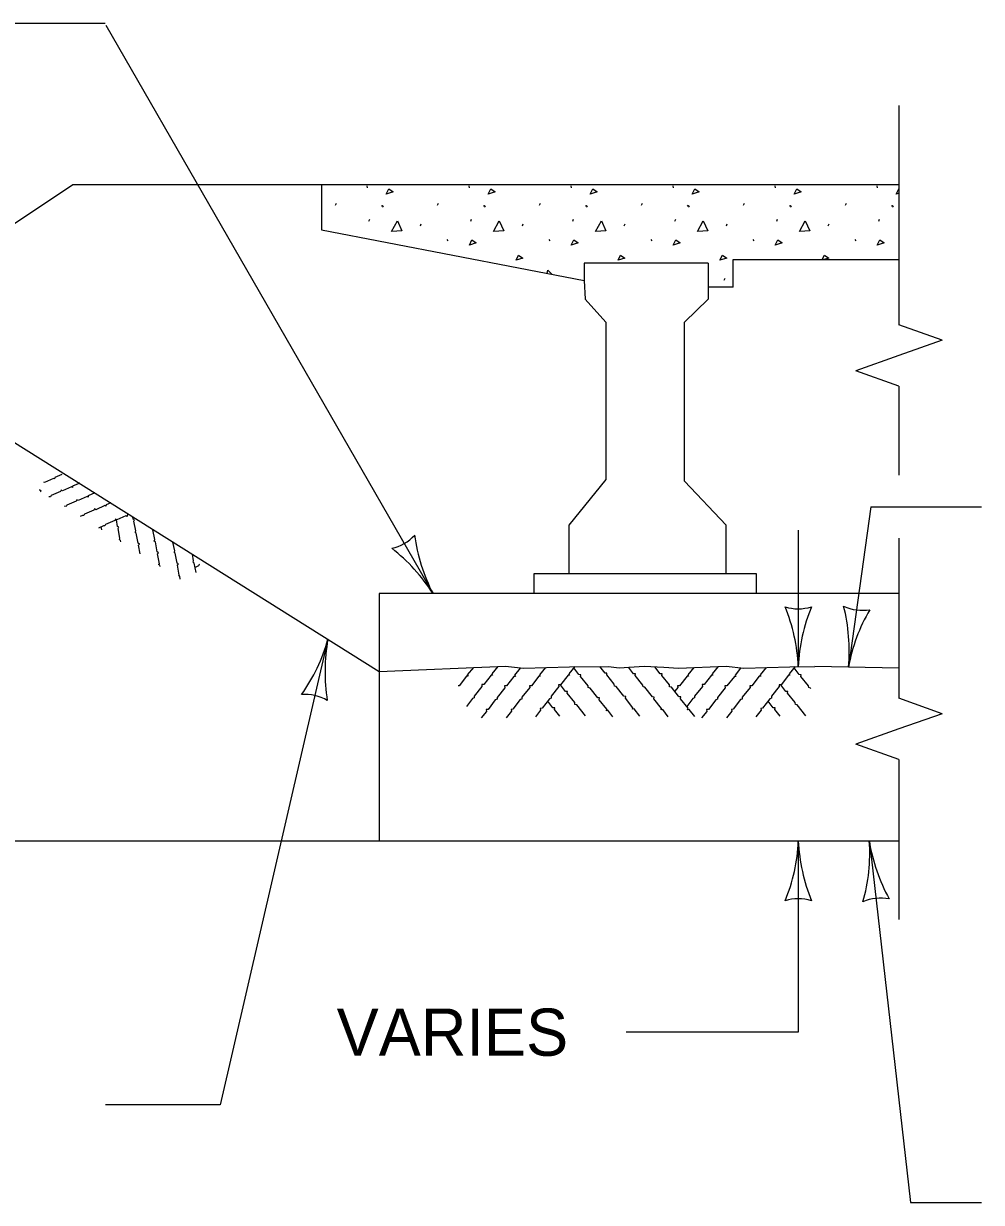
# Model space of a CAD drawing. Extents: x 49991.4 to 50021, y 49987.6 to 50011.4.
# Drawn here: x 50005.968 to 50007.186, y 50005.606 to 50007.104 of the extents above; entities that cross this region are included whole.
import ezdxf

# ---------------------------------------------------------------- set-up
doc = ezdxf.new("R2010")
doc.units = 0
for name, color, linetype in [('Level 1', 7, 'Continuous'), ('Level 2', 7, 'Continuous'), ('Level 3', 7, 'Continuous'), ('Level 4', 7, 'Continuous'), ('Level 6', 7, 'Continuous')]:
    doc.layers.add(name, color=color, linetype=linetype)

msp = doc.modelspace()

# ---------------------------------------------------------------- linework, layer by layer
at = {"layer": 'Level 1'}
for p, q in [((50005.6313, 50006.6335), (50006.0307, 50006.8995)), ((50006.0307, 50006.8995), (50006.3466, 50006.8995)), ((50006.3466, 50006.8995), (50007.0807, 50006.8995)), ((50006.3466, 50006.8995), (50006.3466, 50006.8416)), ((50006.4043, 50006.8976), (50006.4046, 50006.8951)), ((50006.534, 50006.8976), (50006.5342, 50006.8951)), ((50006.6636, 50006.8976), (50006.6639, 50006.8951)), ((50006.7933, 50006.8976), (50006.7935, 50006.8951)), ((50006.9229, 50006.8976), (50006.9232, 50006.8951)), ((50007.0526, 50006.8976), (50007.0529, 50006.8951)), ((50006.3646, 50006.873), (50006.3657, 50006.8754)), ((50006.4228, 50006.873), (50006.4239, 50006.8714)), ((50006.4239, 50006.8724), (50006.4249, 50006.8707)), ((50006.4942, 50006.873), (50006.4953, 50006.8754)), ((50006.5524, 50006.873), (50006.5535, 50006.8714)), ((50006.5535, 50006.8724), (50006.5546, 50006.8707)), ((50006.6239, 50006.873), (50006.625, 50006.8754)), ((50006.6821, 50006.873), (50006.6832, 50006.8714)), ((50006.6832, 50006.8724), (50006.6843, 50006.8707)), ((50006.7535, 50006.873), (50006.7546, 50006.8754)), ((50006.8117, 50006.873), (50006.8128, 50006.8714)), ((50006.8128, 50006.8724), (50006.8139, 50006.8707)), ((50006.8832, 50006.873), (50006.8843, 50006.8754)), ((50006.9414, 50006.873), (50006.9425, 50006.8714)), ((50006.9425, 50006.8724), (50006.9436, 50006.8707)), ((50007.0129, 50006.873), (50007.0139, 50006.8754)), ((50007.0711, 50006.873), (50007.0721, 50006.8714)), ((50007.0721, 50006.8724), (50007.0732, 50006.8707)), ((50006.4068, 50006.8529), (50006.4079, 50006.8554)), ((50006.4723, 50006.8467), (50006.4734, 50006.8491)), ((50006.5365, 50006.8529), (50006.5375, 50006.8554)), ((50006.602, 50006.8467), (50006.6031, 50006.8491)), ((50006.6661, 50006.8529), (50006.6672, 50006.8554)), ((50006.7316, 50006.8467), (50006.7327, 50006.8491)), ((50006.7958, 50006.8529), (50006.7969, 50006.8554)), ((50006.8613, 50006.8467), (50006.8624, 50006.8491)), ((50006.9254, 50006.8529), (50006.9265, 50006.8554)), ((50006.9909, 50006.8467), (50006.992, 50006.8491)), ((50007.0551, 50006.8529), (50007.0562, 50006.8554)), ((50006.3466, 50006.8416), (50006.6807, 50006.7771)), ((50006.5061, 50006.8294), (50006.5072, 50006.8277)), ((50006.6358, 50006.8294), (50006.6369, 50006.8277)), ((50006.7655, 50006.8294), (50006.7665, 50006.8277)), ((50006.8951, 50006.8294), (50006.8962, 50006.8277)), ((50007.0248, 50006.8294), (50007.0259, 50006.8277)), ((50006.8699, 50006.7689), (50006.8699, 50006.8038)), ((50006.8699, 50006.8038), (50007.0807, 50006.8038)), ((50006.6807, 50006.7995), (50006.6807, 50006.7771)), ((50006.8383, 50006.7995), (50006.6807, 50006.7995)), ((50006.8383, 50006.7995), (50006.8383, 50006.7537)), ((50006.6807, 50006.7771), (50006.6818, 50006.7537)), ((50006.8586, 50006.7779), (50006.8597, 50006.7804)), ((50006.8699, 50006.7689), (50006.8383, 50006.7689)), ((50006.6818, 50006.7537), (50006.7083, 50006.7244)), ((50006.8383, 50006.7537), (50006.8083, 50006.7244)), ((50006.7083, 50006.7244), (50006.7083, 50006.5244)), ((50006.8083, 50006.5222), (50006.8083, 50006.7244)), ((50005.8202, 50006.6567), (50006.4201, 50006.2806)), ((50006.7083, 50006.5244), (50006.6612, 50006.4665)), ((50006.8083, 50006.5222), (50006.8612, 50006.4665)), ((50006.6612, 50006.4665), (50006.6612, 50006.405)), ((50006.8612, 50006.405), (50006.8612, 50006.4665)), ((50006.6171, 50006.3795), (50006.6171, 50006.405)), ((50006.6171, 50006.405), (50006.8994, 50006.405)), ((50006.6612, 50006.405), (50006.8612, 50006.405)), ((50006.8994, 50006.405), (50006.8994, 50006.3795)), ((50007.0807, 50006.3795), (50006.4201, 50006.3795)), ((50006.4201, 50006.3795), (50006.4201, 50006.2806)), ((50007.0807, 50006.2848), (50006.9738, 50006.2869))]:
    msp.add_line(p, q, dxfattribs=at)
for points in [[(50006.429, 50006.8871), (50006.4323, 50006.8938), (50006.4377, 50006.8898), (50006.429, 50006.8871)], [(50006.5587, 50006.8871), (50006.5619, 50006.8938), (50006.5673, 50006.8898), (50006.5587, 50006.8871)], [(50006.6883, 50006.8871), (50006.6916, 50006.8938), (50006.697, 50006.8898), (50006.6883, 50006.8871)], [(50006.818, 50006.8871), (50006.8212, 50006.8938), (50006.8266, 50006.8898), (50006.818, 50006.8871)], [(50006.9476, 50006.8871), (50006.9509, 50006.8938), (50006.9563, 50006.8898), (50006.9476, 50006.8871)], [(50007.0773, 50006.8871), (50007.0805, 50006.8938), (50007.0807, 50006.8937)], [(50007.0807, 50006.8881), (50007.0773, 50006.8871)], [(50006.4358, 50006.8394), (50006.4431, 50006.8532), (50006.4488, 50006.8405), (50006.436, 50006.8394)], [(50006.5654, 50006.8394), (50006.5727, 50006.8532), (50006.5784, 50006.8405), (50006.5657, 50006.8394)], [(50006.6951, 50006.8394), (50006.7024, 50006.8532), (50006.7081, 50006.8405), (50006.6954, 50006.8394)], [(50006.8247, 50006.8394), (50006.832, 50006.8532), (50006.8377, 50006.8405), (50006.825, 50006.8394)], [(50006.9544, 50006.8394), (50006.9617, 50006.8532), (50006.9674, 50006.8405), (50006.9547, 50006.8394)], [(50006.5346, 50006.8223), (50006.5378, 50006.8291), (50006.5432, 50006.825), (50006.5346, 50006.8223)], [(50006.6642, 50006.8223), (50006.6675, 50006.8291), (50006.6729, 50006.825), (50006.6642, 50006.8223)], [(50006.7939, 50006.8223), (50006.7971, 50006.8291), (50006.8025, 50006.825), (50006.7939, 50006.8223)], [(50006.9235, 50006.8223), (50006.9268, 50006.8291), (50006.9322, 50006.825), (50006.9235, 50006.8223)], [(50007.0532, 50006.8223), (50007.0564, 50006.8291), (50007.0618, 50006.825), (50007.0532, 50006.8223)], [(50006.5939, 50006.803), (50006.5972, 50006.8097), (50006.6026, 50006.8057), (50006.5939, 50006.803)], [(50006.7236, 50006.803), (50006.7268, 50006.8097), (50006.7322, 50006.8057), (50006.7236, 50006.803)], [(50006.8532, 50006.803), (50006.8565, 50006.8097), (50006.8619, 50006.8057), (50006.8532, 50006.803)], [(50006.9832, 50006.8038), (50006.9861, 50006.8097), (50006.9915, 50006.8057), (50006.9854, 50006.8038)], [(50006.6337, 50006.7861), (50006.6343, 50006.7906), (50006.6398, 50006.785)], [(50006.0166, 50006.5306), (50006.0075, 50006.5269), (50006.0074, 50006.5252), (50006.0061, 50006.5259), (50005.9945, 50006.5208), (50005.9936, 50006.5212)], [(50006.0393, 50006.5198), (50006.0302, 50006.5161), (50006.0302, 50006.5144), (50006.0288, 50006.5151), (50006.0173, 50006.51), (50006.0155, 50006.5109), (50006.0148, 50006.5091), (50006.003, 50006.504), (50006.0021, 50006.5023), (50006.0003, 50006.5026), (50006.0001, 50006.5025)], [(50005.9896, 50006.509), (50005.9903, 50006.5098), (50005.9887, 50006.5109), (50005.9885, 50006.5117)], [(50006.0586, 50006.5074), (50006.0502, 50006.5039), (50006.0501, 50006.5022), (50006.0488, 50006.5029), (50006.0372, 50006.4978), (50006.0355, 50006.4987), (50006.0348, 50006.4969), (50006.023, 50006.4918), (50006.0221, 50006.4902), (50006.0202, 50006.4904), (50006.0198, 50006.4901)], [(50006.0787, 50006.4946), (50006.0727, 50006.4922), (50006.0726, 50006.4906), (50006.0713, 50006.4913), (50006.0597, 50006.4861), (50006.0579, 50006.4871), (50006.0573, 50006.4853), (50006.0454, 50006.4802), (50006.0446, 50006.4785), (50006.0427, 50006.4788), (50006.0399, 50006.4775)], [(50006.1018, 50006.4801), (50006.0994, 50006.4792), (50006.0994, 50006.4775), (50006.098, 50006.4782), (50006.0865, 50006.4731), (50006.0847, 50006.474), (50006.084, 50006.4722), (50006.0722, 50006.4671), (50006.0713, 50006.4654), (50006.0695, 50006.4657), (50006.0633, 50006.4628)], [(50006.0916, 50006.4451), (50006.0912, 50006.4469), (50006.0898, 50006.4482), (50006.0904, 50006.4499), (50006.088, 50006.4622), (50006.0891, 50006.4637), (50006.0874, 50006.4647), (50006.086, 50006.4732)], [(50006.1159, 50006.4299), (50006.1138, 50006.4409), (50006.1151, 50006.4424), (50006.1135, 50006.4435), (50006.1112, 50006.4561), (50006.1098, 50006.4574), (50006.1104, 50006.4591), (50006.108, 50006.4714), (50006.1091, 50006.473), (50006.1074, 50006.4739), (50006.1069, 50006.4769)], [(50006.0674, 50006.4603), (50006.0667, 50006.4644)], [(50006.1415, 50006.4139), (50006.1411, 50006.4158), (50006.1395, 50006.4163), (50006.1405, 50006.4174), (50006.1381, 50006.4298), (50006.1394, 50006.4313), (50006.1378, 50006.4324), (50006.1355, 50006.4451), (50006.1341, 50006.4463), (50006.1348, 50006.448), (50006.1323, 50006.4604), (50006.1327, 50006.4608)], [(50006.167, 50006.3978), (50006.1664, 50006.4016), (50006.1647, 50006.402), (50006.1657, 50006.4031), (50006.1634, 50006.4155), (50006.1647, 50006.4171), (50006.1631, 50006.4181), (50006.1608, 50006.4308), (50006.1594, 50006.432), (50006.16, 50006.4338), (50006.1578, 50006.445)], [(50006.1871, 50006.4063), (50006.1849, 50006.4181), (50006.1835, 50006.4194), (50006.1841, 50006.4211), (50006.1825, 50006.4296)], [(50006.1919, 50006.4159), (50006.191, 50006.4164), (50006.1904, 50006.4146), (50006.1859, 50006.4127)], [(50006.4201, 50006.2806), (50006.5807, 50006.2873), (50006.6035, 50006.2848), (50006.662, 50006.2866), (50006.7114, 50006.287), (50006.725, 50006.2852), (50006.757, 50006.2874), (50006.7817, 50006.2859), (50006.8005, 50006.2848)], [(50006.5397, 50006.2856), (50006.532, 50006.2763), (50006.5329, 50006.2745), (50006.5311, 50006.2745), (50006.5216, 50006.2624), (50006.5203, 50006.2624)], [(50006.5708, 50006.2869), (50006.5632, 50006.2777), (50006.5641, 50006.2759), (50006.5623, 50006.2759), (50006.5528, 50006.2638), (50006.5503, 50006.2638), (50006.5506, 50006.2614), (50006.5408, 50006.2492), (50006.5408, 50006.2469), (50006.5386, 50006.2461), (50006.5309, 50006.2361)], [(50006.5993, 50006.2846), (50006.5922, 50006.276), (50006.5931, 50006.2742), (50006.5913, 50006.2742), (50006.5818, 50006.2621), (50006.5793, 50006.2621), (50006.5796, 50006.2598), (50006.5698, 50006.2475), (50006.5698, 50006.2452), (50006.5676, 50006.2444), (50006.5583, 50006.2323), (50006.556, 50006.2321), (50006.5564, 50006.2298), (50006.5497, 50006.2215)], [(50006.6316, 50006.2857), (50006.6239, 50006.2763), (50006.6248, 50006.2745), (50006.6229, 50006.2745), (50006.6134, 50006.2624), (50006.611, 50006.2624), (50006.6113, 50006.2601), (50006.6014, 50006.2478), (50006.6014, 50006.2455), (50006.5993, 50006.2447), (50006.5899, 50006.2326), (50006.5876, 50006.2324), (50006.5881, 50006.2301), (50006.5813, 50006.2218)], [(50006.6686, 50006.2867), (50006.661, 50006.2776), (50006.6619, 50006.2757), (50006.6601, 50006.2757), (50006.6506, 50006.2636), (50006.6481, 50006.2636), (50006.6484, 50006.2613), (50006.6386, 50006.249), (50006.6386, 50006.2467), (50006.6365, 50006.2459), (50006.6271, 50006.2338), (50006.6248, 50006.2336), (50006.6252, 50006.2313), (50006.6185, 50006.223)], [(50006.717, 50006.223), (50006.7108, 50006.2312), (50006.7088, 50006.2307), (50006.7092, 50006.2325), (50006.6995, 50006.2445), (50006.7001, 50006.2469), (50006.6978, 50006.2472), (50006.688, 50006.2595), (50006.6858, 50006.26), (50006.6855, 50006.2623), (50006.6758, 50006.2741), (50006.6762, 50006.2764), (50006.6738, 50006.2765), (50006.6673, 50006.285)], [(50006.7513, 50006.2238), (50006.7441, 50006.2332), (50006.7421, 50006.2327), (50006.7425, 50006.2345), (50006.7329, 50006.2465), (50006.7334, 50006.2489), (50006.7311, 50006.2491), (50006.7214, 50006.2615), (50006.7191, 50006.262), (50006.7189, 50006.2643), (50006.7092, 50006.2761), (50006.7095, 50006.2784), (50006.7072, 50006.2785), (50006.7006, 50006.2869)], [(50006.7875, 50006.2229), (50006.7804, 50006.2323), (50006.7784, 50006.2318), (50006.7788, 50006.2336), (50006.7691, 50006.2456), (50006.7697, 50006.248), (50006.7674, 50006.2482), (50006.7576, 50006.2606), (50006.7554, 50006.2611), (50006.7551, 50006.2633), (50006.7454, 50006.2752), (50006.7458, 50006.2775), (50006.7434, 50006.2776), (50006.7369, 50006.286)], [(50006.8005, 50006.2492), (50006.7914, 50006.2607), (50006.7892, 50006.2612), (50006.7889, 50006.2635), (50006.7792, 50006.2754), (50006.7796, 50006.2777), (50006.7772, 50006.2777), (50006.7703, 50006.2866)], [(50006.8005, 50006.2848), (50006.8609, 50006.2873), (50006.8837, 50006.2848), (50006.9422, 50006.2866), (50006.9738, 50006.2869)], [(50006.8199, 50006.2856), (50006.8122, 50006.2763), (50006.8131, 50006.2745), (50006.8113, 50006.2745), (50006.8018, 50006.2624), (50006.8005, 50006.2624)], [(50006.851, 50006.2869), (50006.8434, 50006.2777), (50006.8443, 50006.2759), (50006.8425, 50006.2759), (50006.833, 50006.2638), (50006.8305, 50006.2638), (50006.8308, 50006.2614), (50006.821, 50006.2492), (50006.821, 50006.2469), (50006.8188, 50006.2461), (50006.8111, 50006.2361)], [(50006.8795, 50006.2846), (50006.8724, 50006.276), (50006.8733, 50006.2742), (50006.8715, 50006.2742), (50006.862, 50006.2621), (50006.8595, 50006.2621), (50006.8598, 50006.2598), (50006.85, 50006.2475), (50006.85, 50006.2452), (50006.8478, 50006.2444), (50006.8385, 50006.2323), (50006.8362, 50006.2321), (50006.8366, 50006.2298), (50006.8299, 50006.2215)], [(50006.9118, 50006.2857), (50006.9041, 50006.2763), (50006.905, 50006.2745), (50006.9031, 50006.2745), (50006.8936, 50006.2624), (50006.8912, 50006.2624), (50006.8915, 50006.2601), (50006.8816, 50006.2478), (50006.8816, 50006.2455), (50006.8795, 50006.2447), (50006.8701, 50006.2326), (50006.8678, 50006.2324), (50006.8683, 50006.2301), (50006.8615, 50006.2218)], [(50006.9488, 50006.2867), (50006.9412, 50006.2776), (50006.9421, 50006.2757), (50006.9403, 50006.2757), (50006.9308, 50006.2636), (50006.9283, 50006.2636), (50006.9286, 50006.2613), (50006.9188, 50006.249), (50006.9188, 50006.2467), (50006.9167, 50006.2459), (50006.9073, 50006.2338), (50006.905, 50006.2336), (50006.9054, 50006.2313), (50006.8987, 50006.223)], [(50006.9689, 50006.2586), (50006.9682, 50006.2595), (50006.966, 50006.26), (50006.9657, 50006.2623), (50006.956, 50006.2741), (50006.9564, 50006.2764), (50006.954, 50006.2765), (50006.9475, 50006.285)], [(50006.6822, 50006.2242), (50006.6712, 50006.2381), (50006.6689, 50006.2387), (50006.6686, 50006.2409), (50006.659, 50006.2528), (50006.6593, 50006.2551), (50006.6569, 50006.2551), (50006.6505, 50006.2635)], [(50006.8005, 50006.2624), (50006.7993, 50006.2624), (50006.7996, 50006.2601), (50006.7959, 50006.2555)], [(50006.9624, 50006.2242), (50006.9514, 50006.2381), (50006.9491, 50006.2387), (50006.9488, 50006.2409), (50006.9392, 50006.2528), (50006.9395, 50006.2551), (50006.9371, 50006.2551), (50006.9307, 50006.2635)], [(50006.8212, 50006.2232), (50006.8141, 50006.2324), (50006.8121, 50006.2319), (50006.8126, 50006.2337), (50006.8029, 50006.2457), (50006.8035, 50006.2481), (50006.8011, 50006.2484), (50006.8005, 50006.2492)], [(50006.6497, 50006.2236), (50006.6428, 50006.2321), (50006.6432, 50006.2343), (50006.6408, 50006.2344), (50006.6342, 50006.243)], [(50006.9299, 50006.2236), (50006.923, 50006.2321), (50006.9234, 50006.2343), (50006.921, 50006.2344), (50006.9144, 50006.243)]]:
    msp.add_lwpolyline(points, dxfattribs=at)
at = {"layer": 'Level 3'}
for p, q in [((50006.0717, 50007.1038), (50005.6267, 50007.1038)), ((50006.4884, 50006.3795), (50006.0729, 50007.1014)), ((50007.0449, 50006.4898), (50007.0165, 50006.286)), ((50007.0449, 50006.4898), (50007.1856, 50006.4898)), ((50006.9528, 50006.4601), (50006.9528, 50006.2867)), ((50006.3548, 50006.3216), (50006.2177, 50005.7298)), ((50006.9528, 50006.0652), (50006.9528, 50005.822)), ((50007.0431, 50006.0646), (50007.0954, 50005.6059)), ((50006.9528, 50005.822), (50006.7339, 50005.822)), ((50006.2177, 50005.7298), (50006.072, 50005.7298)), ((50007.0954, 50005.6059), (50007.1856, 50005.6059))]:
    msp.add_line(p, q, dxfattribs=at)
for centre, radius, start, end in [((50006.4245, 50006.4906), 0.0548, 282.0625, 317.7849), ((50006.6855, 50006.4823), 0.2223, 187.3797, 207.5632), ((50006.2925, 50006.2534), 0.233, 32.751, 52.0009), ((50006.9528, 50006.4149), 0.0548, 252.1388, 287.8612), ((50006.7201, 50006.2752), 0.233, 2.8273, 22.0772), ((50007.1749, 50006.2775), 0.2223, 157.456, 177.6395), ((50007.0342, 50006.413), 0.0548, 244.2157, 279.9381), ((50006.7845, 50006.3067), 0.233, 354.9042, 14.154), ((50007.2353, 50006.2463), 0.2223, 149.5329, 169.7164), ((50006.1405, 50006.3806), 0.2223, 324.4161, 344.5996), ((50006.5841, 50006.2802), 0.233, 169.7874, 189.0372), ((50006.3259, 50006.1966), 0.0548, 59.0989, 94.8212), ((50006.7307, 50006.0743), 0.2223, 337.456, 357.6395), ((50007.1855, 50006.0767), 0.233, 182.8273, 202.0772), ((50006.8213, 50006.0491), 0.2223, 343.9608, 4.1443), ((50007.2729, 50006.1029), 0.233, 189.3321, 208.5819), ((50007.0576, 50005.9378), 0.0548, 78.6436, 114.3659), ((50006.9528, 50005.937), 0.0548, 72.1388, 107.8612)]:
    msp.add_arc(centre, radius, start, end, dxfattribs=at)
at = {"layer": 'Level 4'}
for p, q in [((50006.4201, 50006.2806), (50006.4201, 50006.0652)), ((50005.8202, 50006.0652), (50007.0807, 50006.0652))]:
    msp.add_line(p, q, dxfattribs=at)
at = {"layer": 'Level 6'}
for p, q in [((50007.0807, 50006.9995), (50007.0807, 50006.7209)), ((50007.1355, 50006.7014), (50007.0807, 50006.7209)), ((50007.1355, 50006.7014), (50007.0807, 50006.682)), ((50007.0807, 50006.682), (50007.0259, 50006.6626)), ((50007.0807, 50006.6431), (50007.0259, 50006.6626)), ((50007.0807, 50006.6431), (50007.0807, 50006.5298)), ((50007.0807, 50006.4498), (50007.0807, 50006.2464)), ((50007.1355, 50006.2269), (50007.0807, 50006.2464)), ((50007.1355, 50006.2269), (50007.0807, 50006.2075)), ((50007.0807, 50006.2075), (50007.0259, 50006.1881)), ((50007.0807, 50006.1686), (50007.0259, 50006.1881)), ((50007.0807, 50006.1686), (50007.0807, 50005.9652))]:
    msp.add_line(p, q, dxfattribs=at)

# ---------------------------------------------------------------- texts
at = {"layer": 'Level 2'}
msp.add_text('VARIES', height=0.06, dxfattribs=at).set_placement((50006.3659, 50005.7922))

doc.saveas('drawing.dxf')
